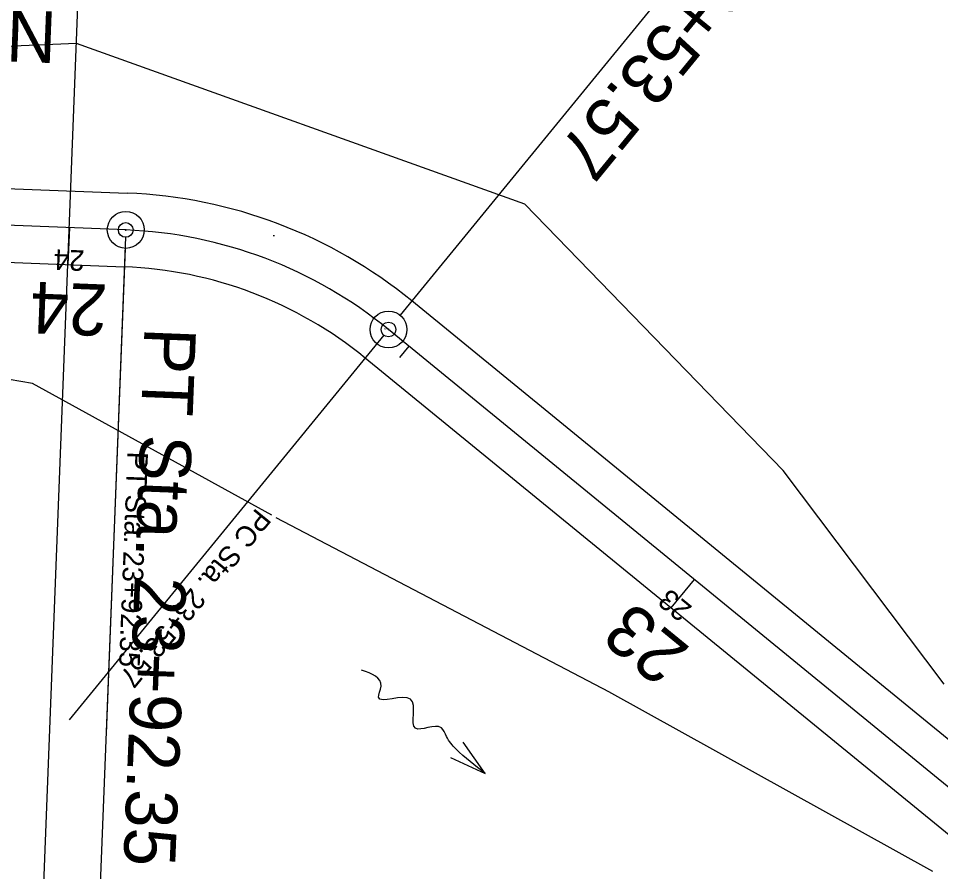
# Model space of a CAD drawing. Extents: x 2399886 to 2513208, y 556821 to 592417.
# Drawn here: x 2446076.4 to 2446201.4, y 557896.1 to 558011.8 of the extents above; entities that cross this region are included whole.
import ezdxf

# ---------------------------------------------------------------- set-up
doc = ezdxf.new("R2010")
doc.units = 0
for name, color, linetype in [('GM_X_Interchange_Ramps', 7, 'Continuous'), ('GM_X_Major_River', 7, 'Continuous'), ('GM_X_Major_River_Text', 7, 'Continuous'), ('GM_X_Section', 7, 'Continuous'), ('GM_X_Township', 7, 'Continuous'), ('GM_X_US_Shield', 7, 'Continuous'), ('SH_Data', 7, 'Continuous')]:
    doc.layers.add(name, color=color, linetype=linetype)

msp = doc.modelspace()

# ---------------------------------------------------------------- linework, layer by layer
at = {"layer": 'GM_X_Interchange_Ramps'}
for p, q in [((2446084.25, 558008.4), (2446027.21, 558006.04)), ((2446145.05, 557986.6), (2446084.25, 558008.4)), ((2446180.1, 557950.48), (2446145.05, 557986.6)), ((2446078.25, 557962.29), (2446066.05, 557964.33)), ((2446110.75, 557944.43), (2446078.25, 557962.29)), ((2446201.93, 557921.48), (2446180.1, 557950.48)), ((2446156.55, 557920.39), (2446111.32, 557944.07)), ((2446200.39, 557896.07), (2446156.46, 557920.44))]:
    msp.add_line(p, q, dxfattribs=at)
at = {"layer": 'GM_X_Major_River'}
for p, q in [((2446197.67, 558056.59), (2446128.14, 557971.55)), ((2446090.92, 557983.12), (2446022.86, 557985.77)), ((2446083.27, 557983.41), (2446083.08, 557978.42)), ((2446090.82, 557980.62), (2446086.73, 557875.79)), ((2446555.11, 557619.22), (2446126.56, 557969.61)), ((2446168.03, 557935.71), (2446164.86, 557931.84))]:
    msp.add_line(p, q, dxfattribs=at)
for centre in [(2446090.92, 557983.12), (2446126.56, 557969.61)]:
    msp.add_circle(centre, 2.5, dxfattribs=at)
msp.add_arc((2446088.58, 557923.16), 60, 50.7295, 87.7664, dxfattribs=at)
at = {"layer": 'GM_X_Major_River_Text'}
for p, q in [((2446076.38, 557806.75), (2446097.2, 558340.62)), ((2446083.08, 557978.42), (2446083.27, 557983.41))]:
    msp.add_line(p, q, dxfattribs=at)
at = {"layer": 'GM_X_Section'}
for p, q in [((2446021.95, 557990.81), (2446091.11, 557988.11)), ((2446042.58, 557980), (2446090.72, 557978.12)), ((2446558.5, 557622.9), (2446129.72, 557973.48)), ((2446551.72, 557615.53), (2446123.39, 557965.74))]:
    msp.add_line(p, q, dxfattribs=at)
for radius in [65, 55]:
    msp.add_arc((2446088.58, 557923.16), radius, 50.7295, 87.7664, dxfattribs=at)
at = {"layer": 'GM_X_Township'}
for p, q in [((2446090.85, 557983.05), (2446090.98, 557983.18)), ((2446090.85, 557983.18), (2446090.98, 557983.05)), ((2446090.92, 557983.19), (2446090.92, 557983.05)), ((2446090.99, 557983.12), (2446090.85, 557983.12)), ((2446111.07, 557982.33), (2446110.93, 557982.33)), ((2446111, 557982.4), (2446111, 557982.26)), ((2446126.49, 557969.55), (2446126.62, 557969.68)), ((2446126.49, 557969.68), (2446126.62, 557969.55)), ((2446126.63, 557969.61), (2446126.49, 557969.61)), ((2446126.56, 557969.68), (2446126.56, 557969.54)), ((2446088.65, 557923.16), (2446088.51, 557923.16)), ((2446088.58, 557923.23), (2446088.58, 557923.09))]:
    msp.add_line(p, q, dxfattribs=at)
msp.add_arc((2446088.58, 557923.16), 60, 50.7295, 87.7664, dxfattribs=at)
at = {"layer": 'GM_X_US_Shield'}
for p, q in [((2446139.68, 557909.37), (2446136.71, 557913.61)), ((2446134.99, 557911.55), (2446139.68, 557909.37))]:
    msp.add_line(p, q, dxfattribs=at)
msp.add_spline([(2446139.68, 557909.37), (2446135.71, 557912.71), (2446134.44, 557914.39), (2446133.73, 557915.58), (2446130.22, 557915.52), (2446129.55, 557919.44), (2446125.22, 557919.71), (2446125.57, 557921.24), (2446122.91, 557923.41)], degree=3, dxfattribs=at)
at = {"layer": 'SH_Data'}
for p, q in [((2446090.92, 557983.12), (2446022.86, 557985.77)), ((2446083.27, 557983.41), (2446083.19, 557981.42)), ((2446090.88, 557982.12), (2446088.25, 557914.82)), ((2446555.11, 557619.22), (2446126.56, 557969.61)), ((2446125.92, 557968.84), (2446083.25, 557916.65)), ((2446129.32, 557967.36), (2446128.05, 557965.81)), ((2446168.03, 557935.71), (2446166.76, 557934.16))]:
    msp.add_line(p, q, dxfattribs=at)
for centre in [(2446090.92, 557983.12), (2446126.56, 557969.61)]:
    msp.add_circle(centre, 1, dxfattribs=at)
msp.add_arc((2446088.58, 557923.16), 60, 50.7295, 87.7664, dxfattribs=at)

# ---------------------------------------------------------------- texts
at = {"layer": 'GM_X_Major_River'}
for s, rotation, p in [('PC Sta. 23+53.57', 230.7295, (2446196.02, 558051.14)), ('N 87%%d 45\' 59" W', 177.7664, (2446081.65, 558012.73)), ('24', 177.7664, (2446088.54, 557975.7)), ('PT Sta. 23+92.35', 267.7664, (2446093.47, 557969.98)), ('23', 140.7295, (2446167.67, 557926.31))]:
    msp.add_text(s, height=7, rotation=rotation, dxfattribs=at).set_placement(p)
at = {"layer": 'GM_X_Township'}
for s, p in [('TEMP8', (2446090.32, 557983.12)), ('TEMP7', (2446125.96, 557969.61))]:
    msp.add_text(s, height=0.14, dxfattribs=at).set_placement(p)
at = {"layer": 'SH_Data'}
for s, rotation, p in [('24', 177.7664, (2446085.38, 557980.33)), ('PT Sta. 23+92.35', 267.7664, (2446091.15, 557953.08)), ('PC Sta. 23+53.57', 230.7295, (2446108.65, 557945.5)), ('23', 140.7295, (2446167.88, 557931.95))]:
    msp.add_text(s, height=2.8, rotation=rotation, dxfattribs=at).set_placement(p)

doc.saveas('drawing.dxf')
